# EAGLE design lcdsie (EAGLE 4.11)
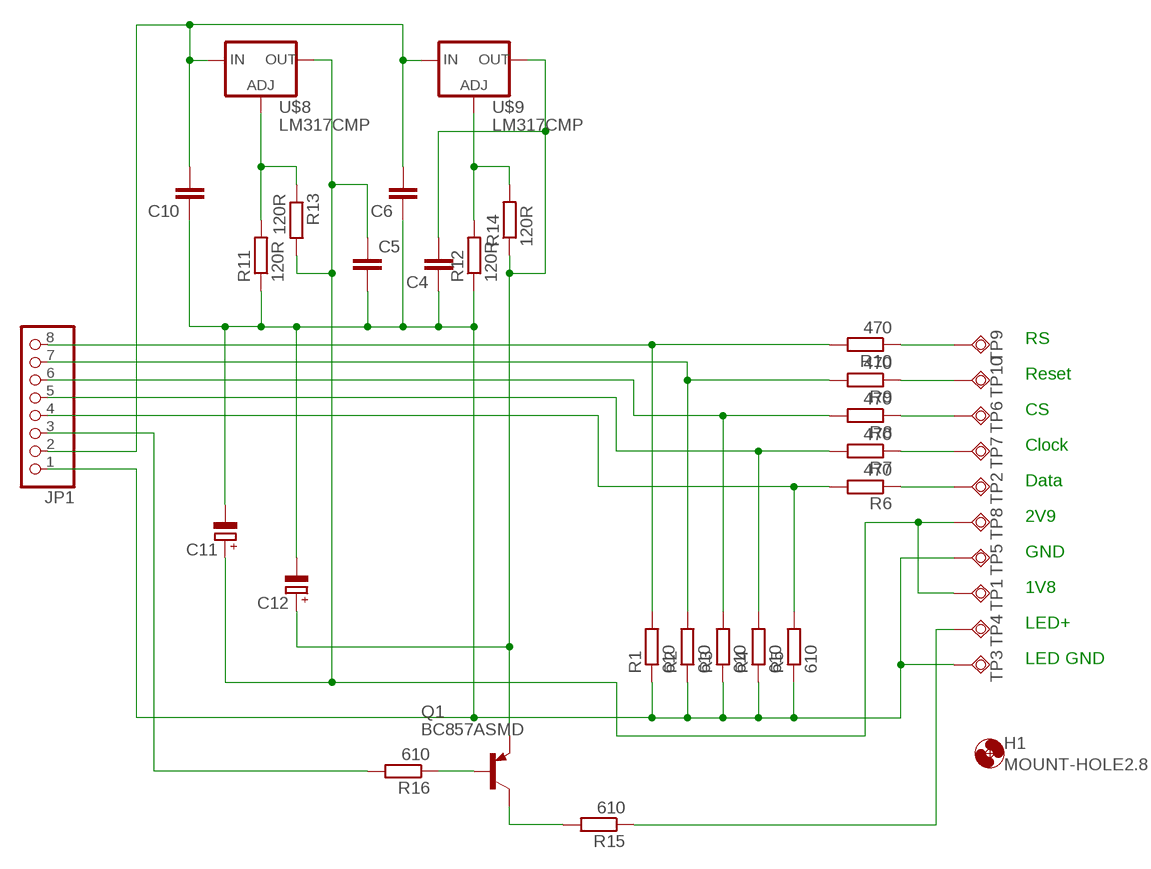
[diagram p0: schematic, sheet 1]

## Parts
C4  C-EUC0805  [C0805]
C5  C-EUC0805  [C0805]
C6  C-EUC0805  [C0805]
C10  C-EUC0805  [C0805]
C11  CPOL-EUA/3216-18R  [A/3216-18R]
C12  CPOL-EUA/3216-18R  [A/3216-18R]
H1  MOUNT-HOLE2.8  [2,8]
JP1  PINHD-1X8  [1X08]
Q1  BC857ASMD  [SOT23-BEC]
R1  610  R-EU_R0603  [R0603]
R2  610  R-EU_R0603  [R0603]
R3  610  R-EU_R0603  [R0603]
R4  610  R-EU_R0603  [R0603]
R5  610  R-EU_R0603  [R0603]
R6  470  R-EU_R0603  [R0603]
R7  470  R-EU_R0603  [R0603]
R8  470  R-EU_R0603  [R0603]
R9  470  R-EU_R0603  [R0603]
R10  470  R-EU_R0603  [R0603]
R11  120R  R-EU_R0805  [R0805]
R12  120R  R-EU_R0805  [R0805]
R13  120R  R-EU_R0805  [R0805]
R14  120R  R-EU_R0805  [R0805]
R15  610  R-EU_R0603  [R0603]
R16  610  R-EU_R0603  [R0603]
TP1  TPSQTP20SQ  [TP20SQ]
TP2  TPSQTP20SQ  [TP20SQ]
TP3  TPSQTP20SQ  [TP20SQ]
TP4  TPSQTP20SQ  [TP20SQ]
TP5  TPSQTP20SQ  [TP20SQ]
TP6  TPSQTP20SQ  [TP20SQ]
TP7  TPSQTP20SQ  [TP20SQ]
TP8  TPSQTP20SQ  [TP20SQ]
TP9  TPSQTP20SQ  [TP20SQ]
TP10  TPSQTP20SQ  [TP20SQ]
U$8  LM317CMP  [SOT223]
U$9  LM317CMP  [SOT223]

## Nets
GND: C4.2 C5.1 C6.2 C10.2 C11.- C12.- JP1.1 R1.1 R2.1 R3.1 R4.1 R5.1 R11.1 R12.1 TP3.TP TP5.TP
N$1: JP1.4 R5.2 R6.2
N$2: JP1.5 R4.2 R7.2
N$3: JP1.6 R3.2 R8.2
N$4: JP1.7 R2.2 R9.2
N$5: JP1.8 R1.2 R10.2
N$6: JP1.3 R16.2
N$7: R10.1 TP9.TP
N$8: R9.1 TP10.TP
N$9: R8.1 TP6.TP
N$10: R7.1 TP7.TP
N$11: R6.1 TP2.TP
N$13: Q1.C R15.2
N$14: R15.1 TP4.TP
N$15: C6.1 C10.1 JP1.2 U$8.3(IN) U$9.3(IN)
N$16: R11.2 R13.1 U$8.1(ADJ)
N$17: Q1.B R16.1
N$18: R12.2 R14.2 U$9.1(ADJ)
N$42: C4.1 C12.+ Q1.E R14.1 U$9.2(OUT)
N$45: C5.2 C11.+ R13.2 TP1.TP TP8.TP U$8.2(OUT)

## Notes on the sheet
- RS
- Reset
- CS
- Clock
- Data
- 2V9
- GND
- 1V8
- LED+
- LED GND

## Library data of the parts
C4-C6 C10 = rcl:C-EU: CAPACITOR, European symbol
C11 C12 = rcl:CPOL-EU: POLARIZED CAPACITOR, European symbol
H1 = holes:MOUNT-HOLE: MOUNTING HOLE with drill center marker
JP1 = pinhead:PINHD-1X8: PIN HEADER
Q1 = transistor-pnp:BC857*: PNP Transistror
R1-R16 = rcl:R-EU_: RESISTOR, European symbol
TP1-TP10 = testpad:TPSQ
U$8 U$9 = !cb04:LM317CMP

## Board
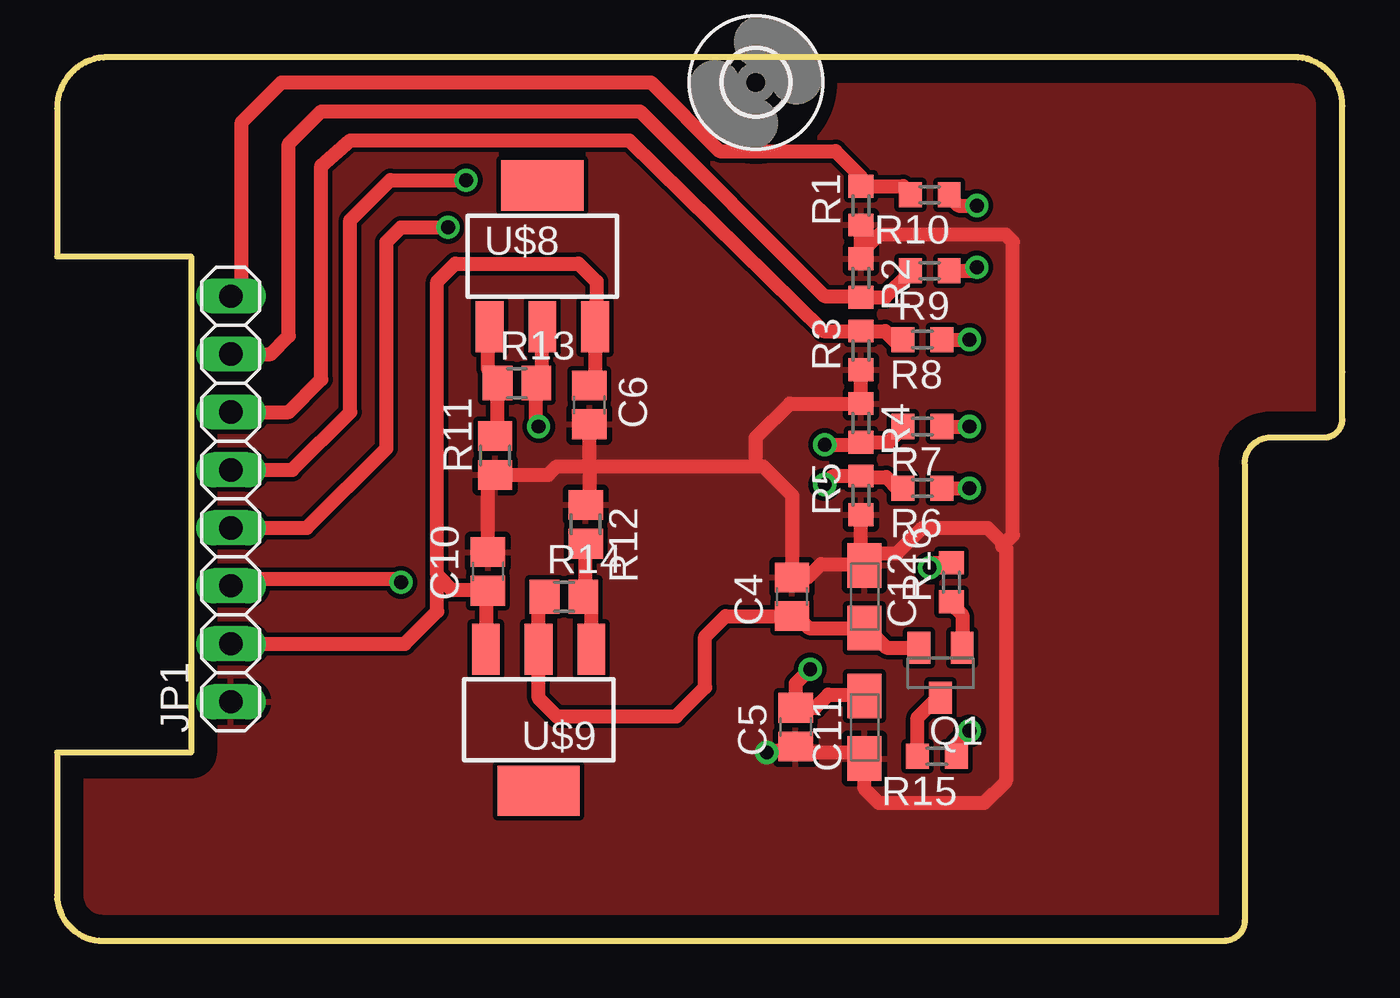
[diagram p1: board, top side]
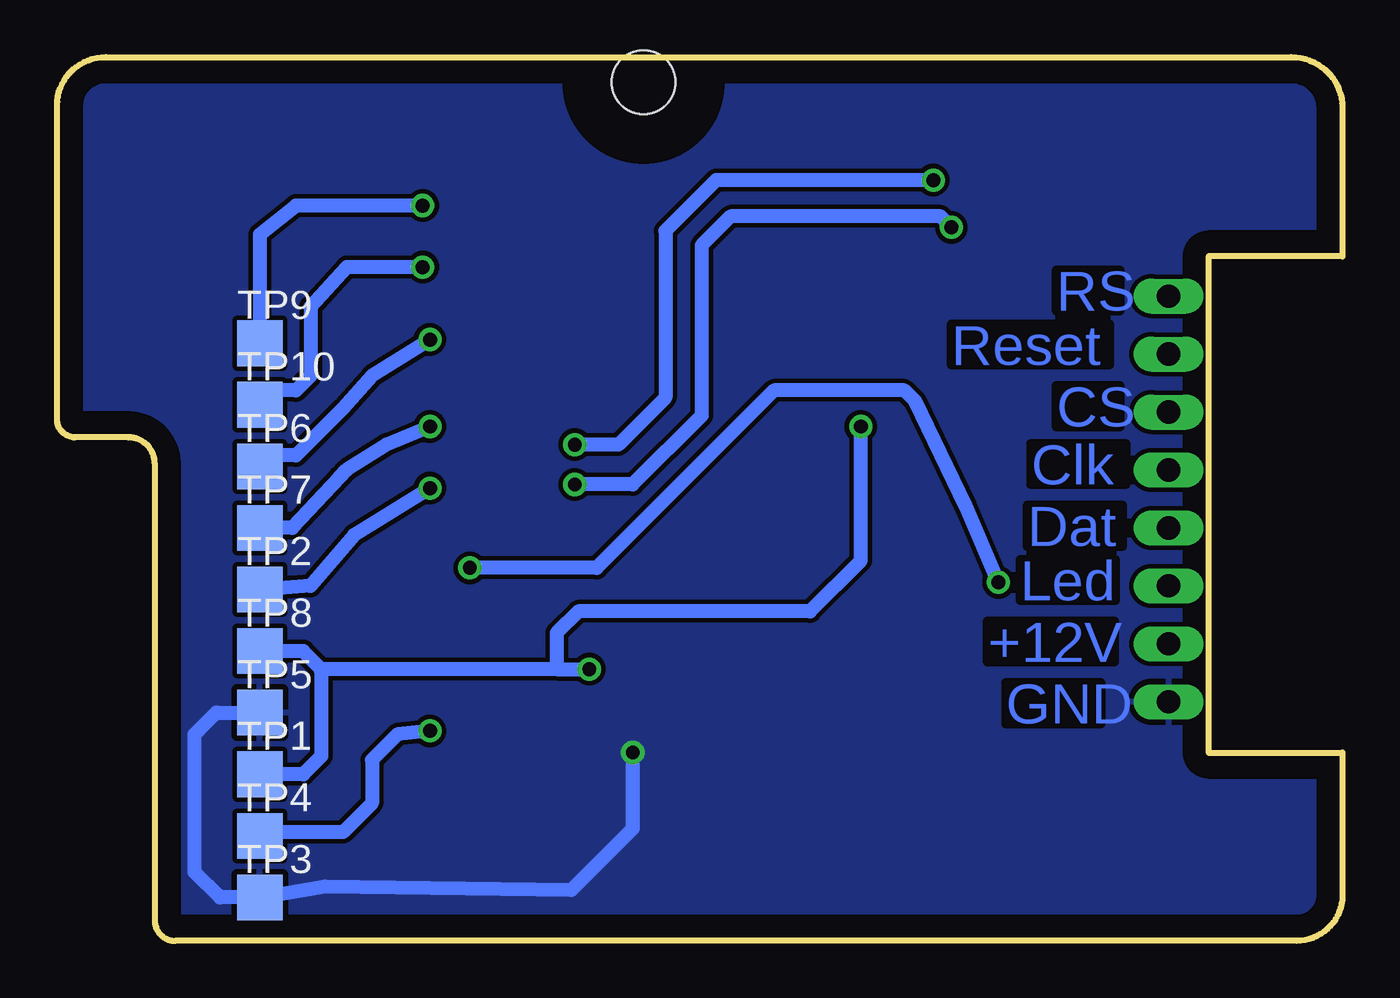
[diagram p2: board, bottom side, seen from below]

Size 56.36 x 38.74 mm. Coordinates in mm from the lower left corner, seen from the top.
Outline: 0,2.02 arc90 2.02,0 51.17,0 arc90 52.07,0.9 52.07,20.92 arc-90 53.21,22.07 55.56,22.07 arc90 56.36,22.86 56.36,24.92 56.36,36.6 arc90 54.22,38.73 2.24,38.73 arc90 0,36.49 0,30 5.87,30 5.87,8.26 0,8.26 0,2.02
Copper layers (1*16): Top 0.035mm / dielectric 1.5mm / Bottom 0.035mm
Design rules "default": minimum track width 10mil, minimum drill 24mil, track to track 8mil, track to pad 8mil, pad to pad 8mil, via to via 8mil, smd to smd 8mil, copper to edge 40mil, drill to drill 8mil, minimum pad ring 10mil, minimum via ring 8mil, stop-mask expansion 4mil, vias tented up to drill 0mil, thermal gap 10mil

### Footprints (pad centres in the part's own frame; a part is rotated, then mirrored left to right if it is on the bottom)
C0805 = smd 1.3 x 1.5: 1 -0.85,0; 2 0.85,0
A/3216-18R = smd 1.95 x 1.5: + 1.375,0; - -1.375,0
2,8 = hole 2.8: 0,0
1X08 = drill 1.016 long: 1 -8.89,0; 2 -6.35,0; 3 -3.81,0; 4 -1.27,0; 5 1.27,0; 6 3.81,0; 7 6.35,0; 8 8.89,0
SOT23-BEC = smd 1 x 1.4: B -0.95,-1.1; C 0,1.1; E 0.95,-1.1
R0603 = smd 1 x 1.1: 1 -0.85,0; 2 0.85,0
R0805 = smd 1.3 x 1.5: 1 -0.85,0; 2 0.85,0
TP20SQ = smd 2 x 2: TP 0,0
SOT223 = smd 1.219 x 2.235: 1 -2.311,-3.099; 2 0,-3.099; 3 2.311,-3.099 | smd 3.6 x 2.2: 4 0,3.099

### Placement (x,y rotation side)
C4  32.23,15.08 90 top
C5  32.39,9.37 90 top
C6  23.34,23.5 270 top
C10  18.89,16.19 90 top
C11  35.4,9.37 90 top
C12  35.4,15.08 270 top
H1  30.64,37.62 0 top
JP1  7.62,19.37 90 top
Q1  38.73,11.75 180 top
R1  35.24,32.23 90 top
R2  35.24,29.05 270 top
R3  35.24,25.88 90 top
R4  35.24,22.7 270 top
R5  35.24,19.53 90 top
R6  37.94,19.84 180 top
R7  37.94,22.54 180 top
R8  37.94,26.35 180 top
R9  38.26,29.37 180 top
R10  38.26,32.7 180 top
R11  19.21,21.27 90 top
R12  23.18,18.26 270 top
R13  20.16,24.45 0 top
R14  22.22,15.08 0 top
R15  38.58,8.1 180 top
R16  39.21,15.72 90 top
TP1  47.47,7.3 0 bottom
TP2  47.47,15.4 0 bottom
TP3  47.47,1.9 0 bottom
TP4  47.47,4.6 0 bottom
TP5  47.47,10 0 bottom
TP6  47.47,20.8 0 bottom
TP7  47.47,18.1 0 bottom
TP8  47.47,12.7 0 bottom
TP9  47.47,26.19 0 bottom
TP10  47.47,23.5 0 bottom
U$8  21.27,30 0 top
U$9  21.11,9.68 180 top

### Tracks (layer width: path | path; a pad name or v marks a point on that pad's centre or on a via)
GND  (via drill 0.61)
  Top 0.61: 35.24,30 R2.1 35.24,30.16 36.04,30.96 41.59,30.96 41.91,30.64 41.91,17.78 41.51,17.38 | 35.24,30 R1.1 | 35.24,30 | 35.24,25.08 | 35.24,25.08 R3.1 | 35.24,25.08 R4.1 32.12,23.55 30.72,22.15 | 35.24,25.08 | 35.4,16.51 | 35.4,16.51 C12.- 35.35,16.46 35.24,16.35 35.08,16.51 33.5,16.51 32.92,15.93 C4.2 32.23,19.53 30.96,20.8 30.64,20.8 | 35.24,16.99 35.24,16.67 35.4,16.51 | 35.24,16.99 R5.1 | 32.6,8.52 C5.1 | 35.4,7.94 | 35.4,7.94 C11.- 35.4,6.67 36.04,6.03 40.64,6.03 41.59,6.99 41.59,17.3 41.51,17.38 | 35.4,7.94 35.08,8.26 32.86,8.26 32.6,8.52 | C10.2 18.89,20.16 19.15,20.42 R11.1 21.53,20.42 21.91,20.8 23.34,20.8 | 23.18,19.05 | 23.18,19.05 R12.1 | 23.34,20.8 23.34,19.21 23.18,19.05 | 23.34,20.8 C6.2 | 41.51,17.38 40.8,18.1 37.94,18.1 36.83,16.99 35.24,16.99 | 23.34,20.8 | 23.34,20.8 30.64,20.8 | 30.72,22.15 30.64,22.07 30.64,20.8 | 30.72,22.15 | 41.51,17.38 41.43,17.3 | 41.51,17.38 | 32.6,8.52 v31.11,8.26
  Bottom 0.61: TP5.TP 49.37,10 50.32,9.05 50.32,3.02 49.21,1.91 47.62,1.91 47.47,1.75 | 47.47,1.75 | 47.47,1.75 TP3.TP 47.31,1.91 44.61,2.38 33.81,2.22 31.11,4.92 v31.11,8.26
  pour Top: -0.79,39.69 56.99,40.64 57.94,-2.22 57.47,-2.7 -0.79,-2.7
  pour Bottom: -0.79,39.85 -0.16,39.21 57.31,39.21 58.26,38.26 58.26,-2.54 57.78,-3.02 -1.11,-3.02 -0.79,-2.7
N$1  (via drill 0.61)
  Top 0.61: R6.2 36.83,19.84 36.35,20.32 35.56,20.32 35.4,20.48 35.3,20.38 R5.2 34.03,20.38 v33.65,20 | v17.14,31.27 15.08,31.27 14.45,30.64 14.45,21.59 10.95,18.1 JP1.4 | JP1.4
  Bottom 0.61: v33.65,20 31.11,20 28.1,23.02 28.1,30.48 26.83,31.75 17.62,31.75 v17.14,31.27
N$2  (via drill 0.61)
  Top 0.61: R7.2 37.09,22.49 36.46,21.85 R4.2 35.19,21.85 35.08,21.75 v33.65,21.75 | JP1.5 10.32,20.64 12.86,23.18 12.86,31.59 14.6,33.34 v17.94,33.34
  Bottom 0.61: v17.94,33.34 27.46,33.34 29.69,31.11 29.69,23.81 31.75,21.75 v33.65,21.75
N$3
  Top 0.61: R8.2 36.99,26.35 36.83,26.19 36.3,26.73 R3.2 33.6,26.73 25.08,35.08 12.86,35.08 11.59,33.97 11.59,24.61 10.16,23.18 JP1.6
N$4
  Top 0.61: JP1.7 9.37,25.72 10.16,26.51 10.16,34.92 11.59,36.35 25.56,36.35 33.65,28.26 34.92,28.26 35.08,28.1 35.19,28.2 R2.2 36.3,28.2 37.41,29.31 R9.2
N$5
  Top 0.61: JP1.8 | JP1.8 8.1,28.73 8.1,35.88 9.84,37.62 26.03,37.62 29.05,34.61 34.13,34.61 35.24,33.5 R1.2 37.09,33.08 37.46,32.7 R10.2
N$6  (via drill 0.61)
  Top 0.61: R16.2 38.47,16.57 v38.26,16.35 | JP1.3 7.78,15.56 8.1,15.88 14.92,15.88 v15.08,15.72
  Bottom 0.61: v38.26,16.35 32.7,16.35 24.92,24.13 19.21,24.13 18.73,23.65 16.51,19.05 | v15.08,15.72 16.51,19.05 | 16.51,19.05
N$7  (via drill 0.61)
  Top 0.61: 39.05,32.7 | R10.1 39.05,32.7 | v40.32,32.23 39.53,32.23 39.05,32.7
  Bottom 0.61: TP9.TP 47.47,30.96 45.88,32.23 v40.32,32.23
N$8  (via drill 0.61)
  Top 0.61: v40.32,29.53 40.16,29.53 40,29.37 R9.1
  Bottom 0.61: v40.32,29.53 43.66,29.53 45.24,27.78 45.24,24.77 45.88,24.13 46.67,24.13 47.31,23.5 TP10.TP
N$9  (via drill 0.61)
  Top 0.61: 39.85,26.35 v40,26.35 | R8.1 39.85,26.35 | 39.85,26.35
  Bottom 0.61: TP6.TP 46.99,21.27 45.88,21.27 43.81,23.34 42.54,24.77 v40,26.35
N$10  (via drill 0.61)
  Top 0.61: R7.1 v40,22.54
  Bottom 0.61: TP7.TP 46.04,18.1 43.97,20.32 43.66,20.64 41.91,21.75 v40,22.54
N$11  (via drill 0.61)
  Top 0.61: v40,19.84 | R6.1 v40,19.84 | v40,19.84
  Bottom 0.61: TP2.TP 45.24,15.56 43.34,17.78 v40,19.84
N$13
  Top 0.61: Q1.C 38.59,10.65 37.73,9.79 R15.2
N$14  (via drill 0.61)
  Top 0.61: R15.1 39.43,8.63 v40,9.21
  Bottom 0.61: v40,9.21 41.43,9.05 42.54,7.94 42.54,6.03 43.81,4.76 46.99,4.76 47.31,4.45 TP4.TP | TP4.TP
N$15
  Top 0.61: C6.1 23.34,24.45 23.58,24.7 U$8.3 23.65,26.83 23.65,27.94 | 18.89,15.4 C10.1 | U$9.3 18.8,15.31 18.89,15.4 | 18.89,15.4 17.3,15.4 16.75,15.95 | 16.75,15.95 16.67,16.03 16.67,28.89 17.46,29.69 22.86,29.69 23.65,28.89 23.65,27.94 | 23.65,27.94 23.65,28.1 | JP1.2 15.24,13.02 16.67,14.45 16.67,15.88 16.75,15.95
N$16
  Top 0.61: U$8.1 18.96,26.6 19.05,26.51 18.89,26.35 18.89,25.08 19.31,24.66 R13.1 19.31,22.33 19.21,22.23 R11.2
N$17
  Top 0.61: R16.1 39.21,14.76 39.69,14.29 39.69,13.18 39.68,13.17 Q1.B
N$18
  Top 0.61: R14.2 23.07,14.98 23.02,14.92 23.1,14.84 | U$9.1 23.42,14.52 23.1,14.84 | 23.1,14.84 | R12.2 23.18,14.92 23.1,14.84
N$42
  Top 0.61: Q1.E 36.36,12.85 35.51,13.71 C12.+ 32.97,13.71 32.44,14.23 C4.1 29.31,14.23 28.42,13.34 28.42,11.11 27.15,9.84 21.91,9.84 21.11,10.64 21.11,12.86 | R14.1 21.37,14.98 21.43,14.92 21.11,14.61 U$9.2 21.11,12.86 | 21.11,12.86
N$45  (via drill 0.61)
  Top 0.61: 35.4,10.79 | 35.4,10.79 C11.+ | 35.4,10.79 33.81,10.79 33.23,10.22 C5.2 32.38,11.27 v33.02,11.91 | U$8.2 21.27,24.77 21.01,24.5 R13.2 21.01,22.64 v21.11,22.54
  Bottom 0.61: TP1.TP 45.56,7.3 44.77,8.1 44.77,11.75 | 44.77,11.75 44.77,11.91 45.56,12.7 TP8.TP | 34.45,11.91 v33.02,11.91 | 34.45,11.91 44.61,11.91 44.77,11.75 | v21.11,22.54 21.11,16.67 23.34,14.45 33.5,14.45 34.45,13.49 34.45,11.91

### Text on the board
Bottom: RS | Reset | CS | Clk | Dat | Led | +12V | GND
